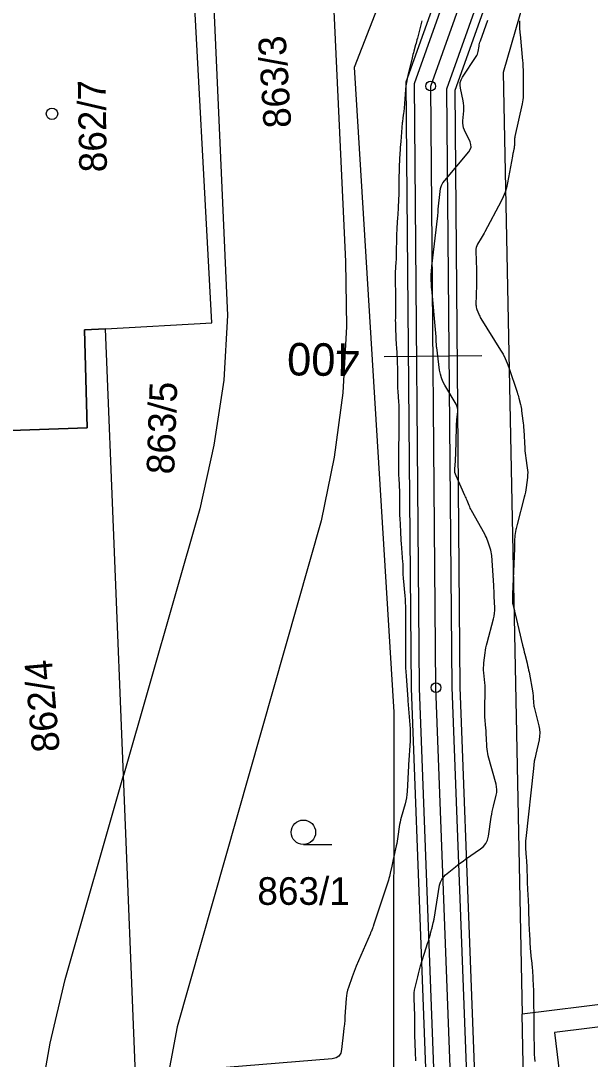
# Model space of a CAD drawing. Extents: x -534481 to -534262, y -1190577 to -1190138.
# Drawn here: x -534358.66 to -534341.14, y -1190186.88 to -1190154.95 of the extents above; entities that cross this region are included whole.
import ezdxf

# ---------------------------------------------------------------- set-up
doc = ezdxf.new("R2010")
doc.units = 0
for name, color, linetype in [('Bonity', 7, 'Continuous'), ('Definiční body', 7, 'Continuous'), ('Polygon budovy', 7, 'Continuous'), ('Polygon parcely', 7, 'Continuous'), ('Vrstva 18', 7, 'Continuous'), ('Vrstva 19', 7, 'Continuous'), ('Vrstva 31', 7, 'Continuous'), ('Vrstva 35', 7, 'Continuous'), ('Vrstva 37', 7, 'Continuous'), ('Vrstva 46', 7, 'Continuous'), ('Vrstva 48', 7, 'Continuous')]:
    doc.layers.add(name, color=color, linetype=linetype)

msp = doc.modelspace()

# ---------------------------------------------------------------- linework, layer by layer
at = {"layer": 'Bonity'}
msp.add_lwpolyline([(-534342.428, -1190234.65), (-534342.865, -1190226.62), (-534344.323, -1190207.198), (-534345.257, -1190192.285), (-534345.89, -1190175.458), (-534346.05, -1190156.962), (-534344.257, -1190151.926), (-534342.463, -1190149.215)], dxfattribs=at)
at = {"layer": 'Definiční body'}
for p, q in [((-534355.5, -1190178.16), (-534356.05, -1190164.42)), ((-534354.73, -1190197.08), (-534355.5, -1190178.16)), ((-534334.79, -1190184.43), (-534343.24, -1190185.5))]:
    msp.add_line(p, q, dxfattribs=at)
for points in [[(-534349.263, -1190148.015), (-534349.33, -1190148.26), (-534348.67, -1190162.35), (-534348.64, -1190164.35), (-534348.75, -1190166.39), (-534349.02, -1190168.37), (-534349.42, -1190170.33), (-534353.85, -1190185.89), (-534354.6, -1190189.86), (-534354.75, -1190192.89), (-534354.73, -1190197.08)], [(-534347.19, -1190196.18), (-534347.17, -1190176.21), (-534348.39, -1190156.38), (-534345.398, -1190148.697)], [(-534341.743, -1190149.341), (-534343.82, -1190156.54), (-534343.24, -1190185.5)], [(-534356.05, -1190164.42), (-534352.78, -1190164.24), (-534353.43, -1190152.26)], [(-534353.43, -1190152.26), (-534352.82, -1190152.23), (-534352.3, -1190164.02), (-534352.41, -1190166), (-534352.72, -1190168), (-534353.15, -1190169.96), (-534355.5, -1190178.16)], [(-534356.05, -1190164.42), (-534356.7, -1190164.46), (-534356.61, -1190167.47), (-534359.85, -1190167.58), (-534360.62, -1190167.61)], [(-534358.42, -1190197.47), (-534358.38, -1190192.4), (-534358.3, -1190190.41), (-534358.1, -1190188.37), (-534357.75, -1190186.39), (-534357.29, -1190184.43), (-534355.5, -1190178.16)], [(-534340.96, -1190232.41), (-534341.05, -1190227.37), (-534341.07, -1190226.16), (-534342.47, -1190212), (-534343.03, -1190195.73), (-534343.24, -1190185.5)]]:
    msp.add_lwpolyline(points, dxfattribs=at)
at = {"layer": 'Polygon parcely'}
for points in [[(-534359.85, -1190167.58), (-534356.61, -1190167.47), (-534356.7, -1190164.46), (-534356.05, -1190164.42), (-534352.78, -1190164.24), (-534353.43, -1190152.26), (-534353.54, -1190152.27), (-534356.53, -1190152.42), (-534360.66, -1190152.64)], [(-534325.28, -1190183.96), (-534342.24, -1190186.06), (-534341.16, -1190195.04), (-534330.16, -1190193.66), (-534328.97, -1190203.08), (-534323, -1190202.33)]]:
    msp.add_lwpolyline(points, close=True, dxfattribs=at)
at = {"layer": 'Vrstva 18'}
msp.add_lwpolyline([(-534346.323, -1190154.95), (-534346.461, -1190155.487), (-534346.474, -1190155.538), (-534346.487, -1190155.588), (-534346.501, -1190155.638), (-534346.514, -1190155.689), (-534346.569, -1190155.89), (-534346.583, -1190155.94), (-534346.596, -1190155.991), (-534346.609, -1190156.041), (-534346.622, -1190156.092), (-534346.755, -1190156.633), (-534346.779, -1190156.739), (-534346.798, -1190156.846), (-534346.813, -1190156.954), (-534346.824, -1190157.062), (-534346.867, -1190157.638), (-534346.87, -1190157.676), (-534346.874, -1190157.715), (-534346.879, -1190157.753), (-534346.884, -1190157.791), (-534346.906, -1190157.942), (-534346.911, -1190157.98), (-534346.916, -1190158.018), (-534346.92, -1190158.056), (-534346.923, -1190158.094), (-534346.972, -1190158.666), (-534346.98, -1190158.755), (-534346.986, -1190158.845), (-534346.992, -1190158.934), (-534346.997, -1190159.024), (-534347.018, -1190159.421), (-534347.021, -1190159.491), (-534347.024, -1190159.562), (-534347.025, -1190159.633), (-534347.026, -1190159.703), (-534347.026, -1190159.986), (-534347.026, -1190160.056), (-534347.027, -1190160.127), (-534347.029, -1190160.198), (-534347.032, -1190160.268), (-534347.052, -1190160.684), (-534347.056, -1190160.764), (-534347.061, -1190160.844), (-534347.066, -1190160.924), (-534347.071, -1190161.004), (-534347.092, -1190161.324), (-534347.097, -1190161.404), (-534347.101, -1190161.484), (-534347.104, -1190161.564), (-534347.105, -1190161.645), (-534347.11, -1190162.055), (-534347.111, -1190162.134), (-534347.114, -1190162.213), (-534347.117, -1190162.292), (-534347.121, -1190162.371), (-534347.141, -1190162.691), (-534347.145, -1190162.768), (-534347.147, -1190162.845), (-534347.147, -1190162.921), (-534347.145, -1190162.998), (-534347.134, -1190163.306), (-534347.132, -1190163.382), (-534347.13, -1190163.459), (-534347.13, -1190163.536), (-534347.131, -1190163.613), (-534347.138, -1190164.091), (-534347.139, -1190164.166), (-534347.138, -1190164.242), (-534347.137, -1190164.317), (-534347.134, -1190164.392), (-534347.122, -1190164.694), (-534347.119, -1190164.769), (-534347.115, -1190164.844), (-534347.111, -1190164.92), (-534347.107, -1190164.995), (-534347.085, -1190165.347), (-534347.081, -1190165.43), (-534347.077, -1190165.513), (-534347.076, -1190165.596), (-534347.075, -1190165.679), (-534347.075, -1190166.01), (-534347.074, -1190166.093), (-534347.072, -1190166.176), (-534347.068, -1190166.259), (-534347.063, -1190166.342), (-534347.04, -1190166.677), (-534347.034, -1190166.761), (-534347.031, -1190166.845), (-534347.029, -1190166.928), (-534347.029, -1190167.012), (-534347.032, -1190167.483), (-534347.033, -1190167.701), (-534347.036, -1190168.065), (-534347.037, -1190168.21), (-534347.037, -1190168.283), (-534347.039, -1190168.668), (-534347.039, -1190168.756), (-534347.038, -1190168.844), (-534347.036, -1190168.933), (-534347.032, -1190169.021), (-534347.012, -1190169.449), (-534347.01, -1190169.515), (-534347.008, -1190169.581), (-534347.007, -1190169.648), (-534347.007, -1190169.714), (-534347.01, -1190169.98), (-534347.01, -1190170.046), (-534347.009, -1190170.112), (-534347.007, -1190170.179), (-534347.004, -1190170.245), (-534346.982, -1190170.661), (-534346.977, -1190170.753), (-534346.972, -1190170.844), (-534346.965, -1190170.936), (-534346.958, -1190171.027), (-534346.913, -1190171.599), (-534346.91, -1190171.64), (-534346.908, -1190171.681), (-534346.907, -1190171.722), (-534346.907, -1190171.763), (-534346.907, -1190171.926), (-534346.906, -1190171.967), (-534346.905, -1190172.008), (-534346.902, -1190172.049), (-534346.899, -1190172.09), (-534346.848, -1190172.635), (-534346.839, -1190172.74), (-534346.833, -1190172.845), (-534346.829, -1190172.95), (-534346.828, -1190173.055), (-534346.828, -1190174.597), (-534346.827, -1190174.721), (-534346.824, -1190174.844), (-534346.818, -1190174.968), (-534346.81, -1190175.091), (-534346.757, -1190175.824), (-534346.757, -1190175.834), (-534346.756, -1190175.855), (-534346.756, -1190175.865), (-534346.694, -1190176.598), (-534346.685, -1190176.721), (-534346.682, -1190176.845), (-534346.682, -1190176.968), (-534346.687, -1190177.092), (-534346.731, -1190177.828), (-534346.732, -1190177.838), (-534346.734, -1190177.854), (-534346.734, -1190177.859), (-534346.777, -1190178.651), (-534346.784, -1190178.747), (-534346.798, -1190178.843), (-534346.816, -1190178.937), (-534346.84, -1190179.031), (-534346.957, -1190179.448), (-534346.976, -1190179.519), (-534346.992, -1190179.591), (-534347.006, -1190179.664), (-534347.017, -1190179.737), (-534347.057, -1190180.031), (-534347.067, -1190180.104), (-534347.079, -1190180.177), (-534347.093, -1190180.25), (-534347.109, -1190180.322), (-534347.202, -1190180.738), (-534347.214, -1190180.791), (-534347.225, -1190180.845), (-534347.237, -1190180.898), (-534347.248, -1190180.951), (-534347.294, -1190181.164), (-534347.307, -1190181.217), (-534347.32, -1190181.269), (-534347.335, -1190181.322), (-534347.351, -1190181.374), (-534347.806, -1190182.759), (-534347.812, -1190182.776), (-534347.818, -1190182.793), (-534347.834, -1190182.836), (-534347.84, -1190182.853), (-534347.844, -1190182.861), (-534347.883, -1190182.961), (-534347.89, -1190182.98), (-534347.898, -1190182.999), (-534347.906, -1190183.018), (-534347.914, -1190183.037), (-534348.339, -1190184.017), (-534348.373, -1190184.098), (-534348.406, -1190184.18), (-534348.437, -1190184.262), (-534348.467, -1190184.345), (-534348.582, -1190184.678), (-534348.608, -1190184.762), (-534348.628, -1190184.847), (-534348.642, -1190184.933), (-534348.651, -1190185.02), (-534348.687, -1190185.565), (-534348.696, -1190185.685), (-534348.706, -1190185.804), (-534348.717, -1190185.924), (-534348.73, -1190186.044), (-534348.789, -1190186.585), (-534348.818, -1190186.7), (-534348.876, -1190186.785), (-534348.962, -1190186.84), (-534349.078, -1190186.866), (-534358.236, -1190187.618)], dxfattribs=at)
at = {"layer": 'Vrstva 19'}
for points in [[(-534346.506, -1190186.933), (-534346.512, -1190186.844), (-534346.517, -1190186.755), (-534346.521, -1190186.667), (-534346.539, -1190186.147), (-534346.541, -1190186.096), (-534346.542, -1190186.045), (-534346.542, -1190185.994), (-534346.541, -1190185.943), (-534346.537, -1190185.739), (-534346.537, -1190185.688), (-534346.537, -1190185.637), (-534346.538, -1190185.586), (-534346.539, -1190185.535), (-534346.56, -1190185.016), (-534346.56, -1190184.93), (-534346.555, -1190184.846), (-534346.544, -1190184.761), (-534346.528, -1190184.678), (-534346.45, -1190184.344), (-534346.43, -1190184.26), (-534346.408, -1190184.177), (-534346.385, -1190184.095), (-534346.36, -1190184.013), (-534346.135, -1190183.297), (-534346.121, -1190183.253), (-534346.107, -1190183.208), (-534346.095, -1190183.162), (-534346.082, -1190183.117), (-534346.024, -1190182.898), (-534346.017, -1190182.871), (-534346.01, -1190182.844), (-534346.003, -1190182.818), (-534345.997, -1190182.791), (-534345.97, -1190182.684), (-534345.964, -1190182.657), (-534345.958, -1190182.63), (-534345.953, -1190182.603), (-534345.948, -1190182.576), (-534345.775, -1190181.533), (-534345.752, -1190181.441), (-534345.713, -1190181.357), (-534345.66, -1190181.282), (-534345.592, -1190181.216), (-534345.288, -1190180.968), (-534345.212, -1190180.907), (-534345.135, -1190180.848), (-534345.056, -1190180.789), (-534344.976, -1190180.733), (-534344.52, -1190180.416), (-534344.427, -1190180.338), (-534344.356, -1190180.247), (-534344.306, -1190180.143), (-534344.277, -1190180.026), (-534344.189, -1190179.436), (-534344.175, -1190179.351), (-534344.159, -1190179.266), (-534344.141, -1190179.181), (-534344.121, -1190179.097), (-534344.037, -1190178.761), (-534344.022, -1190178.677), (-534344.017, -1190178.593), (-534344.023, -1190178.509), (-534344.041, -1190178.425), (-534344.279, -1190177.556), (-534344.296, -1190177.487), (-534344.309, -1190177.417), (-534344.318, -1190177.346), (-534344.323, -1190177.275), (-534344.337, -1190176.988), (-534344.34, -1190176.916), (-534344.345, -1190176.845), (-534344.349, -1190176.773), (-534344.355, -1190176.701), (-534344.381, -1190176.356), (-534344.387, -1190176.275), (-534344.39, -1190176.193), (-534344.39, -1190176.112), (-534344.388, -1190176.03), (-534344.374, -1190175.628), (-534344.373, -1190175.549), (-534344.374, -1190175.471), (-534344.378, -1190175.392), (-534344.385, -1190175.314), (-534344.416, -1190174.999), (-534344.422, -1190174.922), (-534344.423, -1190174.845), (-534344.42, -1190174.768), (-534344.413, -1190174.691), (-534344.376, -1190174.383), (-534344.366, -1190174.307), (-534344.352, -1190174.231), (-534344.336, -1190174.155), (-534344.317, -1190174.08), (-534344.116, -1190173.339), (-534344.097, -1190173.255), (-534344.084, -1190173.171), (-534344.078, -1190173.086), (-534344.079, -1190173.001), (-534344.094, -1190172.657), (-534344.099, -1190172.571), (-534344.103, -1190172.485), (-534344.108, -1190172.4), (-534344.113, -1190172.314), (-534344.172, -1190171.396), (-534344.178, -1190171.339), (-534344.187, -1190171.282), (-534344.201, -1190171.227), (-534344.218, -1190171.172), (-534344.295, -1190170.954), (-534344.316, -1190170.9), (-534344.338, -1190170.846), (-534344.363, -1190170.794), (-534344.39, -1190170.743), (-534344.795, -1190170.01), (-534344.815, -1190169.973), (-534344.833, -1190169.936), (-534344.851, -1190169.898), (-534344.867, -1190169.859), (-534344.931, -1190169.703), (-534344.947, -1190169.664), (-534344.963, -1190169.626), (-534344.98, -1190169.587), (-534344.997, -1190169.549), (-534345.272, -1190168.95), (-534345.292, -1190168.896), (-534345.305, -1190168.842), (-534345.311, -1190168.786), (-534345.31, -1190168.729), (-534345.291, -1190168.499), (-534345.287, -1190168.441), (-534345.283, -1190168.383), (-534345.281, -1190168.325), (-534345.279, -1190168.268), (-534345.259, -1190167.454), (-534345.257, -1190167.393), (-534345.254, -1190167.332), (-534345.249, -1190167.271), (-534345.244, -1190167.21), (-534345.221, -1190166.966), (-534345.22, -1190166.906), (-534345.229, -1190166.849), (-534345.246, -1190166.793), (-534345.272, -1190166.739), (-534345.619, -1190166.153), (-534345.675, -1190166.045), (-534345.72, -1190165.934), (-534345.753, -1190165.819), (-534345.775, -1190165.7), (-534345.867, -1190165.004), (-534345.869, -1190164.988), (-534345.87, -1190164.972), (-534345.872, -1190164.956), (-534345.873, -1190164.94), (-534345.877, -1190164.876), (-534345.878, -1190164.86), (-534345.879, -1190164.844), (-534345.879, -1190164.829), (-534345.88, -1190164.813), (-534345.883, -1190164.739), (-534345.884, -1190164.721), (-534345.885, -1190164.703), (-534345.886, -1190164.686), (-534345.887, -1190164.668), (-534346.02, -1190163.199), (-534346.023, -1190163.164), (-534346.026, -1190163.128), (-534346.028, -1190163.093), (-534346.029, -1190163.057), (-534346.035, -1190162.914), (-534346.035, -1190162.879), (-534346.035, -1190162.845), (-534346.035, -1190162.81), (-534346.033, -1190162.775), (-534346.024, -1190162.637), (-534346.022, -1190162.602), (-534346.019, -1190162.568), (-534346.016, -1190162.533), (-534346.012, -1190162.499), (-534345.831, -1190160.952), (-534345.83, -1190160.941), (-534345.829, -1190160.93), (-534345.828, -1190160.919), (-534345.827, -1190160.909), (-534345.824, -1190160.864), (-534345.823, -1190160.844), (-534345.822, -1190160.825), (-534345.82, -1190160.787), (-534345.82, -1190160.778), (-534345.819, -1190160.768), (-534345.818, -1190160.759), (-534345.817, -1190160.749), (-534345.762, -1190160.199), (-534345.746, -1190160.107), (-534345.717, -1190160.02), (-534345.675, -1190159.939), (-534345.62, -1190159.863), (-534344.88, -1190158.985), (-534344.833, -1190158.913), (-534344.811, -1190158.838), (-534344.813, -1190158.76), (-534344.84, -1190158.678), (-534345.011, -1190158.317), (-534345.039, -1190158.247), (-534345.057, -1190158.174), (-534345.065, -1190158.1), (-534345.063, -1190158.025), (-534345.036, -1190157.718), (-534345.033, -1190157.641), (-534345.034, -1190157.565), (-534345.042, -1190157.49), (-534345.055, -1190157.414), (-534345.138, -1190157.025), (-534345.148, -1190156.936), (-534345.141, -1190156.851), (-534345.116, -1190156.769), (-534345.074, -1190156.691), (-534344.652, -1190156.052), (-534344.63, -1190156.016), (-534344.614, -1190155.979), (-534344.601, -1190155.94), (-534344.592, -1190155.9), (-534344.565, -1190155.735), (-534344.557, -1190155.694), (-534344.547, -1190155.653), (-534344.536, -1190155.613), (-534344.523, -1190155.574), (-534344.293, -1190154.931)], [(-534343.324, -1190154.95), (-534343.318, -1190155.166), (-534343.316, -1190155.219), (-534343.313, -1190155.273), (-534343.309, -1190155.326), (-534343.304, -1190155.38), (-534343.228, -1190156.185), (-534343.222, -1190156.251), (-534343.218, -1190156.317), (-534343.214, -1190156.383), (-534343.212, -1190156.449), (-534343.205, -1190156.713), (-534343.203, -1190156.779), (-534343.203, -1190156.845), (-534343.203, -1190156.91), (-534343.203, -1190156.976), (-534343.206, -1190157.246), (-534343.209, -1190157.313), (-534343.215, -1190157.379), (-534343.224, -1190157.445), (-534343.237, -1190157.51), (-534343.46, -1190158.51), (-534343.466, -1190158.543), (-534343.471, -1190158.576), (-534343.474, -1190158.609), (-534343.476, -1190158.643), (-534343.478, -1190158.789), (-534343.479, -1190158.817), (-534343.482, -1190158.844), (-534343.486, -1190158.871), (-534343.491, -1190158.899), (-534343.515, -1190159.007), (-534343.52, -1190159.034), (-534343.526, -1190159.061), (-534343.531, -1190159.088), (-534343.537, -1190159.116), (-534343.689, -1190159.94), (-534343.721, -1190160.085), (-534343.765, -1190160.226), (-534343.818, -1190160.363), (-534343.883, -1190160.496), (-534344.384, -1190161.439), (-534344.411, -1190161.488), (-534344.438, -1190161.537), (-534344.465, -1190161.586), (-534344.494, -1190161.634), (-534344.608, -1190161.826), (-534344.633, -1190161.875), (-534344.65, -1190161.927), (-534344.66, -1190161.979), (-534344.662, -1190162.034), (-534344.646, -1190162.616), (-534344.644, -1190162.73), (-534344.643, -1190162.845), (-534344.643, -1190162.959), (-534344.645, -1190163.074), (-534344.658, -1190163.685), (-534344.657, -1190163.722), (-534344.652, -1190163.759), (-534344.643, -1190163.795), (-534344.631, -1190163.831), (-534344.575, -1190163.971), (-534344.56, -1190164.006), (-534344.543, -1190164.04), (-534344.526, -1190164.073), (-534344.506, -1190164.105), (-534343.901, -1190165.08), (-534343.826, -1190165.209), (-534343.759, -1190165.341), (-534343.7, -1190165.477), (-534343.648, -1190165.616), (-534343.395, -1190166.372), (-534343.38, -1190166.419), (-534343.365, -1190166.466), (-534343.352, -1190166.513), (-534343.34, -1190166.56), (-534343.291, -1190166.75), (-534343.28, -1190166.797), (-534343.27, -1190166.845), (-534343.262, -1190166.893), (-534343.255, -1190166.942), (-534343.215, -1190167.254), (-534343.206, -1190167.322), (-534343.199, -1190167.391), (-534343.194, -1190167.459), (-534343.189, -1190167.528), (-534343.157, -1190168.1), (-534343.152, -1190168.175), (-534343.145, -1190168.25), (-534343.136, -1190168.324), (-534343.126, -1190168.399), (-534343.081, -1190168.696), (-534343.072, -1190168.77), (-534343.068, -1190168.845), (-534343.07, -1190168.919), (-534343.077, -1190168.994), (-534343.116, -1190169.301), (-534343.126, -1190169.377), (-534343.14, -1190169.452), (-534343.156, -1190169.527), (-534343.174, -1190169.601), (-534343.396, -1190170.439), (-534343.406, -1190170.479), (-534343.415, -1190170.519), (-534343.423, -1190170.56), (-534343.431, -1190170.6), (-534343.459, -1190170.778), (-534343.464, -1190170.811), (-534343.468, -1190170.845), (-534343.47, -1190170.878), (-534343.471, -1190170.912), (-534343.474, -1190171.046), (-534343.475, -1190171.079), (-534343.475, -1190171.112), (-534343.476, -1190171.146), (-534343.478, -1190171.179), (-534343.531, -1190172.583), (-534343.532, -1190172.609), (-534343.533, -1190172.635), (-534343.534, -1190172.661), (-534343.535, -1190172.687), (-534343.537, -1190172.792), (-534343.536, -1190172.818), (-534343.534, -1190172.844), (-534343.531, -1190172.87), (-534343.525, -1190172.895), (-534343.487, -1190173.049), (-534343.478, -1190173.084), (-534343.47, -1190173.118), (-534343.462, -1190173.152), (-534343.454, -1190173.186), (-534343.225, -1190174.155), (-534343.208, -1190174.224), (-534343.191, -1190174.293), (-534343.174, -1190174.362), (-534343.157, -1190174.431), (-534343.086, -1190174.707), (-534343.069, -1190174.776), (-534343.053, -1190174.845), (-534343.039, -1190174.915), (-534343.025, -1190174.985), (-534342.912, -1190175.616), (-534342.906, -1190175.652), (-534342.901, -1190175.689), (-534342.898, -1190175.726), (-534342.895, -1190175.763), (-534342.888, -1190175.912), (-534342.886, -1190175.949), (-534342.881, -1190175.986), (-534342.875, -1190176.022), (-534342.867, -1190176.059), (-534342.724, -1190176.63), (-534342.703, -1190176.737), (-534342.696, -1190176.845), (-534342.701, -1190176.952), (-534342.72, -1190177.06), (-534342.82, -1190177.499), (-534342.843, -1190177.609), (-534342.864, -1190177.719), (-534342.881, -1190177.829), (-534342.894, -1190177.94), (-534343.127, -1190180.095), (-534343.133, -1190180.17), (-534343.136, -1190180.245), (-534343.136, -1190180.32), (-534343.132, -1190180.395), (-534343.11, -1190180.695), (-534343.105, -1190180.77), (-534343.101, -1190180.845), (-534343.098, -1190180.92), (-534343.095, -1190180.995), (-534343.085, -1190181.347), (-534343.083, -1190181.427), (-534343.08, -1190181.507), (-534343.076, -1190181.587), (-534343.072, -1190181.667), (-534343.054, -1190181.987), (-534343.05, -1190182.067), (-534343.047, -1190182.147), (-534343.044, -1190182.227), (-534343.041, -1190182.307), (-534343.032, -1190182.67), (-534343.029, -1190182.757), (-534343.025, -1190182.844), (-534343.021, -1190182.932), (-534343.016, -1190183.019), (-534342.987, -1190183.501), (-534342.983, -1190183.554), (-534342.979, -1190183.607), (-534342.974, -1190183.66), (-534342.968, -1190183.714), (-534342.943, -1190183.926), (-534342.938, -1190183.979), (-534342.933, -1190184.033), (-534342.928, -1190184.086), (-534342.925, -1190184.139), (-534342.898, -1190184.641), (-534342.893, -1190184.743), (-534342.889, -1190184.845), (-534342.886, -1190184.946), (-534342.885, -1190185.048), (-534342.881, -1190185.639), (-534342.881, -1190185.673), (-534342.88, -1190185.707), (-534342.88, -1190185.741), (-534342.88, -1190185.775), (-534342.878, -1190185.91), (-534342.877, -1190185.944), (-534342.877, -1190185.978), (-534342.876, -1190186.012), (-534342.876, -1190186.046), (-534342.872, -1190186.628), (-534342.869, -1190186.736), (-534342.862, -1190186.844), (-534342.85, -1190186.951)]]:
    msp.add_lwpolyline(points, dxfattribs=at)
at = {"layer": 'Vrstva 31'}
msp.add_lwpolyline([(-534344.478, -1190165.258), (-534347.478, -1190165.284)], dxfattribs=at)
at = {"layer": 'Vrstva 35'}
for points in [[(-534343.317, -1190232.109), (-534343.613, -1190226.668), (-534345.072, -1190207.25), (-534346.006, -1190192.323), (-534346.64, -1190175.475), (-534346.801, -1190156.835), (-534344.933, -1190151.588), (-534343.268, -1190149.073)], [(-534343.067, -1190232.098), (-534343.364, -1190226.652), (-534344.822, -1190207.233), (-534345.756, -1190192.31), (-534346.39, -1190175.47), (-534346.551, -1190156.878), (-534344.708, -1190151.701), (-534343, -1190149.12)], [(-534342.068, -1190232.057), (-534342.366, -1190226.587), (-534343.825, -1190207.164), (-534344.757, -1190192.26), (-534345.39, -1190175.446), (-534345.55, -1190157.046), (-534343.807, -1190152.151), (-534341.926, -1190149.309)], [(-534341.818, -1190232.046), (-534342.116, -1190226.571), (-534343.575, -1190207.147), (-534344.507, -1190192.248), (-534345.14, -1190175.441), (-534345.299, -1190157.088), (-534343.581, -1190152.264), (-534341.657, -1190149.357)]]:
    msp.add_lwpolyline(points, dxfattribs=at)
at = {"layer": 'Vrstva 37'}
for centre in [(-534346.05, -1190156.962), (-534346.05, -1190156.962), (-534346.05, -1190156.962), (-534346.05, -1190156.962), (-534346.05, -1190156.962), (-534346.05, -1190156.962), (-534345.89, -1190175.458), (-534345.89, -1190175.458), (-534345.89, -1190175.458), (-534345.89, -1190175.458), (-534345.89, -1190175.458), (-534345.89, -1190175.458)]:
    msp.add_circle(centre, 0.15, dxfattribs=at)
at = {"layer": 'Vrstva 46'}
msp.add_circle((-534357.697, -1190157.813), 0.175, dxfattribs=at)
at = {"layer": 'Vrstva 48'}
msp.add_line((-534349.965, -1190180.279), (-534349.09, -1190180.279), dxfattribs=at)
msp.add_circle((-534349.965, -1190179.904), 0.375, dxfattribs=at)

# ---------------------------------------------------------------- texts
at = {"layer": 'Polygon budovy'}
for s, rotation, p in [('863/3', 93.6145, (-534350.334, -1190158.227)), ('862/7', 91, (-534356.005, -1190159.605)), ('863/5', 88, (-534353.941, -1190168.909)), ('862/4', 95, (-534357.454, -1190177.406))]:
    msp.add_text(s, height=0.85, rotation=rotation, dxfattribs=at).set_placement(p)
msp.add_text('863/1', height=0.85, dxfattribs=at).set_placement((-534351.381, -1190182.136))
at = {"layer": 'Vrstva 31'}
msp.add_text('400', height=1, rotation=179.271, dxfattribs=at).set_placement((-534348.229, -1190164.882))

doc.saveas('drawing.dxf')
